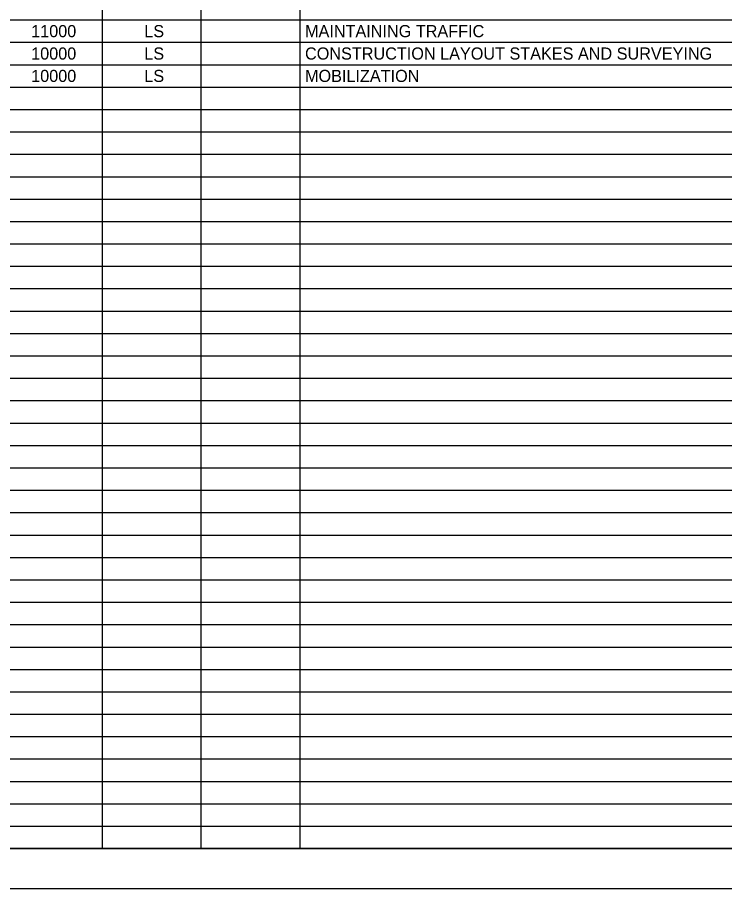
# Model space of a CAD drawing. Extents: x 0 to 34, y 0 to 22.
# Drawn here: x 16.98 to 25.82, y 0 to 10.89 of the extents above; entities that cross this region are included whole.
import ezdxf

# ---------------------------------------------------------------- set-up
doc = ezdxf.new("R2010")
doc.units = 0
for name, color, linetype in [('SH_Border', 7, 'Continuous'), ('SH_Cut_Line', 7, 'Continuous'), ('SH_Text', 7, 'Continuous')]:
    doc.layers.add(name, color=color, linetype=linetype)

msp = doc.modelspace()

# ---------------------------------------------------------------- linework, layer by layer
at = {"layer": 'SH_Border'}
msp.add_lwpolyline([(1.5, 21.5), (33.5, 21.5), (33.5, 0.5), (1.5, 0.5)], close=True, dxfattribs=at)
at = {"layer": 'SH_Cut_Line'}
msp.add_lwpolyline([(0, 0), (34, 0), (34, 22), (0, 22)], close=True, dxfattribs=at)
at = {"layer": 'SH_Text'}
for p, q in [((18.036, 21.5), (18.036, 0.5)), ((19.272, 21.5), (19.272, 0.5)), ((20.507, 21.5), (20.507, 0.5)), ((1.5, 10.86), (32.004, 10.86)), ((1.5, 10.58), (32.004, 10.58)), ((1.5, 10.3), (32.004, 10.3)), ((1.5, 10.02), (32.004, 10.02)), ((1.5, 9.74), (32.004, 9.74)), ((1.5, 9.46), (32.004, 9.46)), ((1.5, 9.18), (32.004, 9.18)), ((1.5, 8.9), (32.004, 8.9)), ((1.5, 8.62), (32.004, 8.62)), ((1.5, 8.34), (32.004, 8.34)), ((1.5, 8.06), (32.004, 8.06)), ((1.5, 7.78), (32.004, 7.78)), ((1.5, 7.5), (32.004, 7.5)), ((1.5, 7.22), (32.004, 7.22)), ((1.5, 6.94), (32.004, 6.94)), ((1.5, 6.66), (32.004, 6.66)), ((1.5, 6.38), (32.004, 6.38)), ((1.5, 6.1), (32.004, 6.1)), ((1.5, 5.82), (32.004, 5.82)), ((1.5, 5.54), (32.004, 5.54)), ((1.5, 5.26), (32.004, 5.26)), ((1.5, 4.98), (32.004, 4.98)), ((1.5, 4.7), (32.004, 4.7)), ((1.5, 4.42), (32.004, 4.42)), ((1.5, 4.14), (32.004, 4.14)), ((1.5, 3.86), (32.004, 3.86)), ((1.5, 3.58), (32.004, 3.58)), ((1.5, 3.3), (32.004, 3.3)), ((1.5, 3.02), (32.004, 3.02)), ((1.5, 2.74), (32.004, 2.74)), ((1.5, 2.46), (32.004, 2.46)), ((1.5, 2.18), (32.004, 2.18)), ((1.5, 1.9), (32.004, 1.9)), ((1.5, 1.62), (32.004, 1.62)), ((1.5, 1.34), (32.004, 1.34)), ((1.5, 1.06), (32.004, 1.06)), ((1.5, 0.78), (32.004, 0.78)), ((1.5, 0.5), (32.004, 0.5))]:
    msp.add_line(p, q, dxfattribs=at)

# ---------------------------------------------------------------- texts
for s, height, p in [('11000', 0.1515, (17.15, 10.644)), ('LS', 0.1515, (18.564, 10.644)), ('MAINTAINING TRAFFIC', 0.15153, (20.573, 10.644)), ('10000', 0.1515, (17.15, 10.364)), ('LS', 0.1515, (18.564, 10.364)), ('CONSTRUCTION LAYOUT STAKES AND SURVEYING', 0.15153, (20.573, 10.364)), ('10000', 0.1515, (17.15, 10.084)), ('LS', 0.1515, (18.564, 10.084)), ('MOBILIZATION', 0.15153, (20.573, 10.084))]:
    msp.add_text(s, height=height, dxfattribs=at).set_placement(p)

doc.saveas('drawing.dxf')
